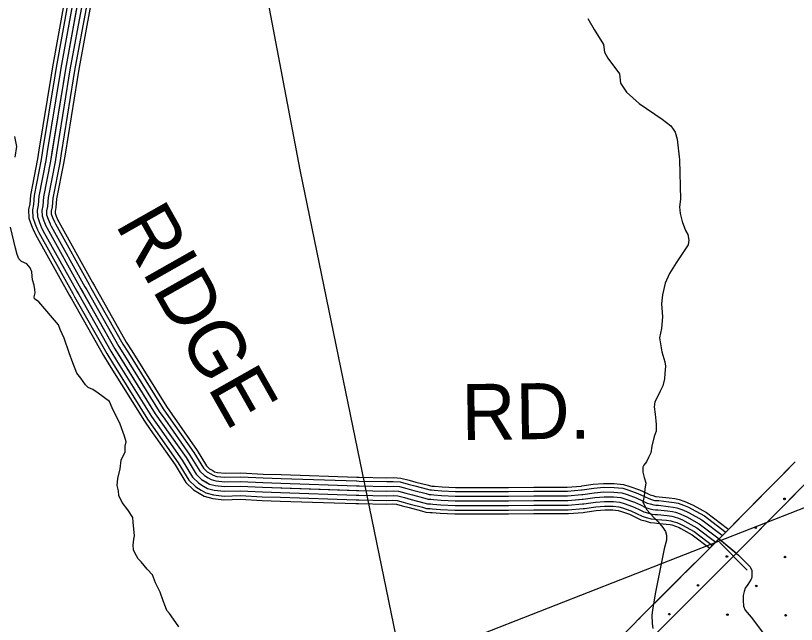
# Model space of a CAD drawing. Extents: x 1577619 to 1828281, y 483481 to 598136.
# Drawn here: x 1684780 to 1689939, y 520679 to 524700 of the extents above; entities that cross this region are included whole.
import ezdxf

# ---------------------------------------------------------------- set-up
doc = ezdxf.new("R2010")
doc.units = 0
for name, color, linetype in [('DESIGN - CENTERLINE - Proposed Text', 7, 'Continuous'), ('DESIGN - CONTOURS - Intermediate with optional Text', 7, 'Continuous'), ('DESIGN - EROSION CONTROL - Devices', 7, 'Continuous'), ('DESIGN - ROW - Right-of-Way and Easement Labels', 7, 'Continuous'), ('DESIGN - TRANSPORTATION - Text', 7, 'Continuous'), ('SURVEY - CENTERLINE - Preliminary Text', 7, 'Continuous'), ('SURVEY - DRAINAGE - Area Shapes', 7, 'Continuous'), ('SURVEY - TRANSPORTATION - Roads', 7, 'Continuous'), ('SURVEY - VEGETATION - Features with Text', 7, 'Continuous')]:
    doc.layers.add(name, color=color, linetype=linetype)

msp = doc.modelspace()

# ---------------------------------------------------------------- linework, layer by layer
at = {"layer": 'DESIGN - CENTERLINE - Proposed Text'}
for q in [(1697294.5, 524306.5), (1695618, 523650.8)]:
    msp.add_line((1681456.9, 518112.3), q, dxfattribs=at)
at = {"layer": 'DESIGN - CONTOURS - Intermediate with optional Text'}
msp.add_line((1689614.1, 521037.7), (1689430.4, 521221.7), dxfattribs=at)
for points in [[(1687255, 518732.8), (1688399.1, 519989.9), (1689031.6, 520639.6), (1689595.9, 521203.2), (1690042.2, 521653.7)], [(1689522.2, 521129.7), (1689595.9, 521203.2), (1689987.2, 521598.1)], [(1689055.2, 520663.3), (1689522.2, 521129.7)]]:
    msp.add_lwpolyline(points, dxfattribs=at)
at = {"layer": 'DESIGN - EROSION CONTROL - Devices'}
for centre in [(1689860.1, 521508.1), (1689669.7, 521317.7), (1689479.3, 521127.3), (1689863.9, 521123.5), (1689288.9, 520936.9), (1689673.5, 520933.1), (1689098.5, 520746.4), (1689483.1, 520742.7), (1689867.6, 520739)]:
    msp.add_circle(centre, 5.28, dxfattribs=at)
at = {"layer": 'DESIGN - TRANSPORTATION - Text'}
for points in [[(1688561.2, 524681), (1688603.3, 524609.7), (1688664.2, 524508.8), (1688671.7, 524458.6), (1688693.3, 524418.2), (1688770.3, 524315.2), (1688775.6, 524254.9), (1688815, 524194.4), (1688900.3, 524119.3), (1689051.3, 524017.4), (1689108.8, 523972.7), (1689124.6, 523950.5), (1689138.4, 523930.3), (1689151.9, 523884), (1689166.5, 523747.5), (1689171.8, 523488.7), (1689167.2, 523436.6), (1689170.7, 523392.5), (1689184.2, 523340.2), (1689205.6, 523279.8), (1689221.3, 523253.6), (1689228.9, 523217.4), (1689224.6, 523187.3), (1689198.2, 523147.5), (1689143.3, 523067.9), (1689100.5, 522996.1), (1689071.8, 522932.3), (1689055, 522856.2), (1689048.3, 522796.1), (1689053.4, 522709.8), (1689046.6, 522633.7), (1689034, 522571.7), (1689049, 522479.3), (1689068.3, 522412.9), (1689074, 522384.7), (1689069.5, 522336.7), (1689067.1, 522300.6), (1689056.6, 522254.6), (1689038.2, 522218.7), (1689019.8, 522178.7), (1689003.5, 522148.8), (1688999.1, 522116.8), (1689004.6, 522068.6), (1689010.2, 522024.4), (1689011.9, 521998.3), (1689011.4, 521956.2), (1688999.1, 521920.3), (1688984.4, 521856.2), (1688975.9, 521812.2), (1688961.5, 521780.3), (1688947.2, 521752.4), (1688931, 521730.5), (1688924.9, 521718.5), (1688924.5, 521684.4), (1688932.1, 521648.2), (1688943.8, 521614), (1688937.3, 521572), (1688932.8, 521525.9), (1688924.4, 521485.9), (1688949.9, 521435.5), (1688997.4, 521384.8), (1689025.1, 521356.5), (1689056.7, 521320), (1689074.4, 521291.8), (1689080.2, 521267.6), (1689079.8, 521235.6), (1689065.2, 521177.6), (1689006.1, 520881.4), (1688986.9, 520773.3), (1688982.5, 520739.2), (1688986, 520685.1), (1688989.6, 520650.9)], [(1684776.5, 523764.5), (1684788.8, 523835.5), (1684773.5, 523901.9)], [(1685499, 521922.9), (1685469.8, 522001.4), (1685416.9, 522110.3), (1685399.4, 522150.6), (1685324.1, 522206.8), (1685290.1, 522229.9), (1685258.3, 522244.3), (1685240.4, 522262.5), (1685210.9, 522305), (1685185.2, 522339.3), (1685157.9, 522405.8), (1685134.6, 522472.2), (1685099.6, 522568.9), (1685074.2, 522627.3), (1685062.5, 522657.5), (1684932, 522809.3), (1684910.2, 522825.5), (1684904.2, 522829.6), (1684902.4, 522843.7), (1684908.7, 522869.7), (1684906.9, 522891.7), (1684901.2, 522919.9), (1684891.6, 522956.1), (1684889.8, 522978.2), (1684886.1, 523008.3), (1684876.4, 523034.5), (1684852.7, 523060.8), (1684818.8, 523077.2), (1684801, 523093.4), (1684789.3, 523121.6), (1684779.7, 523163.8), (1684745.4, 523302.3)], [(1685857.9, 520663.7), (1685822.4, 520714.3), (1685796.8, 520750.6), (1685779, 520770.9), (1685769.2, 520795), (1685755.6, 520835.3), (1685734.2, 520891.7), (1685702.9, 520954.2), (1685683.4, 521006.5), (1685649.8, 521043), (1685610.3, 521091.5), (1685590.5, 521111.8), (1685566.9, 521152.1), (1685559.1, 521172.3), (1685557.4, 521202.4), (1685561.8, 521242.4), (1685564.1, 521264.5), (1685557, 521354.8), (1685553.3, 521384.9), (1685521.8, 521435.4), (1685484.3, 521483.9), (1685460.8, 521530.3), (1685459.1, 521560.4), (1685451.5, 521596.5), (1685454, 521642.6), (1685470.7, 521706.6), (1685477.3, 521762.7), (1685503.9, 521818.6), (1685504.3, 521856.7), (1685510.6, 521884.7), (1685499, 521922.9)]]:
    msp.add_lwpolyline(points, dxfattribs=at)
at = {"layer": 'SURVEY - CENTERLINE - Preliminary Text'}
for points in [[(1687420, 519988), (1686659.5, 523681.4), (1686272.5, 525723.1), (1686266.6, 525758.2), (1686265.3, 525791), (1686255.6, 526135), (1686301.1, 527011.8)], [(1687420, 519988), (1686659.5, 523681.4), (1686272.5, 525723.1), (1686266.6, 525758.2), (1686265.3, 525791), (1686255.6, 526135), (1686275.1, 526510.7)]]:
    msp.add_lwpolyline(points, dxfattribs=at)
at = {"layer": 'SURVEY - DRAINAGE - Area Shapes'}
for points in [[(1689427.4, 521243.8), (1689557.1, 521136.3), (1689630.3, 521061.3), (1689640.2, 521045.2), (1689643.2, 521035.6), (1689644, 521025.1), (1689643.7, 521005), (1689643.2, 520994.2), (1689641.5, 520983), (1689638.9, 520977.2), (1689617.1, 520943.1)], [(1689617.1, 520943.1), (1689600.8, 520919.2), (1689592.6, 520897.3), (1689586.3, 520869.3), (1689586, 520839.2), (1689589.5, 520799), (1689600.6, 520772.2), (1689638.8, 520726.3), (1689814.5, 520495.9), (1690430.1, 519669.2), (1690816.8, 519145.7), (1691181.8, 518654.5), (1691546.8, 518163.4), (1691631.7, 518054.2), (1691660.1, 518016.4)]]:
    msp.add_lwpolyline(points, dxfattribs=at)
at = {"layer": 'SURVEY - TRANSPORTATION - Roads'}
for points in [[(1685193.4, 524810), (1685108.4, 524347.6), (1685009.9, 523739), (1684963.4, 523502.8), (1684958.8, 523444.7), (1684952.4, 523412.7), (1684954.1, 523378.6), (1684965.7, 523344.4), (1684979.4, 523312.1), (1684987.7, 523295.9), (1685211.1, 522894.6), (1685435.1, 522499.2), (1685702.7, 522069.2), (1685905.7, 521780.3), (1685972.6, 521671.3), (1686008.3, 521636.8), (1686060, 521606.2), (1686097.9, 521595.8), (1686159.9, 521589.1), (1686265.9, 521592), (1686412, 521584.4), (1687048.1, 521563.7), (1687231.9, 521559.9), (1687274.2, 521561.3), (1687310.2, 521559), (1687357.1, 521546), (1687402, 521533.9), (1687484.3, 521512.9), (1687505.8, 521506.8), (1687539.8, 521504.4), (1687591.8, 521499.9), (1687683.8, 521494.9), (1688036, 521495.2), (1688204.1, 521497.4), (1688428.2, 521497.1), (1688530.4, 521506), (1688606.6, 521517.3), (1688668.6, 521522.6), (1688730.9, 521522.2), (1688778.7, 521517.5), (1688810.6, 521507.1), (1688868.4, 521486.5), (1688908.2, 521468), (1688942.1, 521451.6), (1688964, 521445.3), (1688989.9, 521437), (1689023.9, 521434.7), (1689087.9, 521428), (1689119.9, 521423.7), (1689139.8, 521419.4), (1689169.7, 521409.1), (1689199.6, 521396.7), (1689215.5, 521388.6), (1689297.1, 521343.6), (1689428.1, 521243.9), (1689544.4, 521146.9)], [(1685103.3, 524799.7), (1685023, 524362.4), (1685013.9, 524306)], [(1685127.6, 524795.3), (1685047.3, 524358.1), (1685038.3, 524302)], [(1685158.1, 524789.7), (1685077.9, 524352.9), (1685068.9, 524297)], [(1685188.6, 524784.1), (1685108.4, 524347.6), (1685099.5, 524292.1)], [(1685219.1, 524778.5), (1685139, 524342.3), (1685130.1, 524287.1)], [(1685249.6, 524772.9), (1685169.5, 524337), (1685160.7, 524282.2)], [(1685274.9, 524768.2), (1685194.9, 524332.7), (1685186, 524278.1)], [(1685013.9, 524306), (1684934, 523812.4)], [(1685038.3, 524302), (1684958.4, 523808.4)], [(1685068.9, 524297.1), (1684989, 523803.5)], [(1685099.5, 524292.1), (1685019.6, 523798.5)], [(1685130.1, 524287.2), (1685050.2, 523793.6)], [(1685160.7, 524282.2), (1685080.8, 523788.6)], [(1685186, 524278.1), (1685106.2, 523784.5)], [(1684934, 523812.4), (1684924.6, 523754.3), (1684877.4, 523514.7), (1684872.7, 523456.6), (1684865.3, 523419.1), (1684868, 523362.2), (1684884.7, 523313.4), (1684900.8, 523275.4), (1684903.5, 523270.2)], [(1684958.4, 523808.4), (1684948.9, 523749.9), (1684901.9, 523511.3), (1684897.3, 523453.2), (1684890.2, 523417.3), (1684892.6, 523366.9), (1684907.8, 523322.2), (1684923.2, 523285.9), (1684925.5, 523281.4)], [(1684989, 523803.5), (1684979.4, 523744.4), (1684932.6, 523507.1), (1684928, 523449), (1684921.3, 523415), (1684923.3, 523372.7), (1684936.7, 523333.3), (1684951.3, 523299), (1684953.1, 523295.6)], [(1685019.6, 523798.5), (1685009.9, 523739), (1684963.4, 523502.8), (1684958.8, 523444.7), (1684952.4, 523412.7), (1684954.1, 523378.6), (1684965.7, 523344.4), (1684979.4, 523312.1), (1684980.6, 523309.7)], [(1685050.2, 523793.6), (1685040.4, 523733.5), (1684994.2, 523498.6), (1684989.5, 523440.5), (1684983.6, 523410.4), (1684984.8, 523384.4), (1684994.7, 523355.4), (1685007.5, 523325.3), (1685008.2, 523323.8)], [(1685080.8, 523788.6), (1685071, 523728), (1685024.9, 523494.3), (1685020.3, 523436.2), (1685014.7, 523408.1), (1685015.6, 523390.3), (1685023.7, 523366.5), (1685035.6, 523338.4), (1685035.8, 523337.9)], [(1685106.2, 523784.5), (1685096.3, 523723.5), (1685050.4, 523490.8), (1685045.8, 523432.7), (1685040.6, 523406.2), (1685041.1, 523395.1), (1685047.7, 523375.7), (1685058.9, 523349.3)], [(1685008.2, 523323.8), (1685015.1, 523310.5), (1685238.1, 522909.8), (1685250.5, 522888)], [(1685035.8, 523338), (1685042.4, 523325.1), (1685265.2, 522924.9), (1685277.5, 522903.2)], [(1685058.7, 523349.7), (1685065.1, 523337.2), (1685287.6, 522937.5), (1685299.8, 522915.9)], [(1684903.5, 523270.2), (1684911.2, 523255), (1685135.5, 522852.1), (1685148.1, 522829.9)], [(1684925.5, 523281.4), (1684933, 523266.7), (1685157.1, 522864.2), (1685169.6, 522842.1)], [(1684953, 523295.6), (1684960.4, 523281.3), (1685184.1, 522879.4), (1685196.5, 522857.4)], [(1684980.6, 523309.7), (1684987.7, 523295.9), (1685211.1, 522894.6), (1685223.5, 522872.7)], [(1685299.8, 522915.9), (1685510.5, 522544), (1685546.9, 522485.5)], [(1685196.5, 522857.4), (1685408.4, 522483.3), (1685446.1, 522422.7)], [(1685223.5, 522872.7), (1685435.1, 522499.2), (1685472.4, 522439.1)], [(1685250.5, 522888), (1685461.7, 522515), (1685498.7, 522455.5)], [(1685277.5, 522903.2), (1685488.4, 522530.8), (1685525.1, 522471.9)], [(1685148.1, 522829.9), (1685360.5, 522454.9), (1685398.8, 522393.3)], [(1685169.6, 522842.1), (1685381.7, 522467.5), (1685419.8, 522406.3)], [(1685498.7, 522455.5), (1685728.5, 522086.3), (1685765, 522034.4)], [(1685525.1, 522471.9), (1685754.4, 522103.4), (1685790.4, 522052.3)], [(1685546.9, 522485.5), (1685775.8, 522117.6), (1685811.4, 522067)], [(1685398.8, 522393.3), (1685630.3, 522021.3), (1685668.7, 521966.7)], [(1685419.8, 522406.4), (1685650.9, 522035), (1685688.9, 521981)], [(1685446.1, 522422.7), (1685676.8, 522052.1), (1685714.3, 521998.8)], [(1685472.4, 522439.1), (1685702.7, 522069.2), (1685739.6, 522016.6)], [(1685765, 522034.4), (1685931.6, 521797.3), (1685997, 521690.8), (1686027.2, 521661.6), (1686053, 521646.3)], [(1685790.3, 522052.3), (1685957.6, 521814.4), (1686021.3, 521710.4), (1686046.1, 521686.5), (1686068.8, 521673)], [(1685811.4, 522067.1), (1685979.1, 521828.5), (1686041.6, 521726.6), (1686061.8, 521707), (1686081.9, 521695.2)], [(1685688.9, 521981), (1685853.9, 521746.2), (1685923.9, 521632.2), (1685970.4, 521587.2), (1686005.6, 521566.3)], [(1685714.3, 521998.8), (1685879.8, 521763.2), (1685948.2, 521651.7), (1685989.3, 521612), (1686021.4, 521593)], [(1685739.6, 522016.6), (1685905.7, 521780.3), (1685972.6, 521671.3), (1686008.3, 521636.8), (1686037.2, 521619.7)], [(1685668.7, 521966.7), (1685833.2, 521732.6), (1685904.4, 521616.6), (1685955.3, 521567.4), (1685993.1, 521545)], [(1686068.8, 521673), (1686084.4, 521663.8), (1686109.5, 521656.9), (1686162.3, 521651.2), (1686266.7, 521654), (1686414.6, 521646.4), (1686533.5, 521642.5)], [(1686081.9, 521695.2), (1686094.6, 521687.7), (1686114.3, 521682.2), (1686163.4, 521676.9), (1686267, 521679.8), (1686415.7, 521672.1), (1686534.3, 521668.2)], [(1686037.2, 521619.7), (1686060, 521606.2), (1686097.9, 521595.8), (1686159.9, 521589.1), (1686265.9, 521592), (1686412, 521584.4), (1686531.4, 521580.5)], [(1686053, 521646.4), (1686072.2, 521635), (1686103.7, 521626.3), (1686161.1, 521620.1), (1686266.3, 521623), (1686413.3, 521615.4), (1686532.5, 521611.5)], [(1686533.4, 521642.5), (1687033.2, 521626.2)], [(1686534.3, 521668.2), (1687034, 521651.9)], [(1687033.1, 521626.2), (1687049.8, 521625.7), (1687231.5, 521622), (1687275.2, 521623.4), (1687320.6, 521620.4), (1687373.4, 521605.8), (1687417.7, 521593.9), (1687500.5, 521572.8), (1687516.5, 521568.2), (1687528.4, 521567.4)], [(1687034, 521651.9), (1687050.4, 521651.4), (1687231.4, 521647.7), (1687275.7, 521649.2), (1687324.9, 521645.9), (1687380.2, 521630.7), (1687424.3, 521618.8), (1687507.2, 521597.6), (1687521, 521593.6), (1687530.2, 521593)], [(1686021.4, 521593), (1686047.8, 521577.4), (1686092.1, 521565.2), (1686158.6, 521558.1), (1686265.6, 521561), (1686410.7, 521553.5), (1686530.4, 521549.6)], [(1686531.4, 521580.5), (1687031.2, 521564.3)], [(1686532.4, 521611.5), (1687032.2, 521595.3)], [(1687032.1, 521595.3), (1687048.9, 521594.7), (1687231.7, 521590.9), (1687274.7, 521592.4), (1687315.4, 521589.7), (1687365.3, 521575.9), (1687409.9, 521563.9), (1687492.4, 521542.8), (1687511.2, 521537.5), (1687526.2, 521536.4)], [(1687528.4, 521567.4), (1687544.6, 521566.2), (1687596.1, 521561.7), (1687685.4, 521556.9), (1688023.6, 521557.2)], [(1687530.1, 521593), (1687546.6, 521591.9), (1687598, 521587.4), (1687686.1, 521582.6), (1688023.6, 521582.9)], [(1688023.6, 521582.9), (1688035.4, 521582.9), (1688203.6, 521585.2), (1688424.5, 521584.8), (1688515.6, 521592.8)], [(1688023.6, 521557.2), (1688035.5, 521557.2), (1688203.7, 521559.4), (1688425.6, 521559.1), (1688517.9, 521567.2)], [(1688515.6, 521592.8), (1688520.2, 521593.2), (1688596.4, 521604.5), (1688665.2, 521610.4), (1688735.5, 521609.9), (1688796.7, 521603.9), (1688838.9, 521590.2), (1688901.7, 521567.7), (1688945.8, 521547.3), (1688973.4, 521533.9), (1688989.4, 521529.3), (1689006.6, 521523.8), (1689012.7, 521523.4)], [(1688517.8, 521567.2), (1688523.2, 521567.6), (1688599.4, 521578.9), (1688666.2, 521584.7), (1688734.2, 521584.1), (1688791.4, 521578.5), (1688830.6, 521565.8), (1688891.9, 521543.9), (1688934.8, 521524), (1688964.2, 521509.7), (1688981.9, 521504.7), (1689001.7, 521498.4), (1689010.9, 521497.7)], [(1685993, 521545.1), (1686025.8, 521525.7), (1686081.7, 521510.3), (1686156.4, 521502.3), (1686264.9, 521505.2), (1686408.3, 521497.8), (1686528.6, 521493.9)], [(1686005.6, 521566.3), (1686035.5, 521548.6), (1686086.3, 521534.7), (1686157.4, 521527), (1686265.2, 521529.9), (1686409.4, 521522.5), (1686529.4, 521518.6)], [(1686529.4, 521518.6), (1687029.1, 521502.3)], [(1686530.4, 521549.6), (1687030.1, 521533.3)], [(1687030.1, 521533.3), (1687047.3, 521532.7), (1687232.1, 521528.9), (1687273.7, 521530.3), (1687305, 521528.2), (1687349, 521516.1), (1687394.1, 521504), (1687476.2, 521483), (1687500.4, 521476.1), (1687521.9, 521474.6)], [(1687031.1, 521564.3), (1687048.1, 521563.7), (1687231.9, 521559.9), (1687274.2, 521561.3), (1687310.2, 521559), (1687357.1, 521546), (1687402, 521533.9), (1687484.3, 521512.9), (1687505.8, 521506.8), (1687524.1, 521505.5)], [(1687526.2, 521536.4), (1687542.2, 521535.3), (1687593.9, 521530.8), (1687684.6, 521525.9), (1688023.7, 521526.2)], [(1688023.6, 521526.2), (1688035.8, 521526.2), (1688203.9, 521528.4), (1688426.9, 521528.1), (1688520.6, 521536.3)], [(1688520.5, 521536.3), (1688526.8, 521536.8), (1688602.9, 521548.1), (1688667.4, 521553.7), (1688732.5, 521553.2), (1688785, 521548), (1688820.6, 521536.5), (1688880.1, 521515.2), (1688921.5, 521496), (1688953.1, 521480.7), (1688973, 521475), (1688995.8, 521467.7), (1689008.8, 521466.8)], [(1688523.3, 521505.4), (1688530.4, 521506), (1688606.6, 521517.3), (1688668.6, 521522.6), (1688730.9, 521522.2), (1688778.7, 521517.5), (1688810.6, 521507.1), (1688868.4, 521486.5), (1688908.2, 521468), (1688942.1, 521451.6), (1688964, 521445.3), (1688989.9, 521437), (1689006.7, 521435.9)], [(1689012.7, 521523.4), (1689031.5, 521522.1), (1689098.4, 521515.1), (1689134.9, 521510.1), (1689163.3, 521504.1), (1689200.8, 521491.1), (1689236.5, 521476.4), (1689256.8, 521466), (1689345.1, 521417.3), (1689482.8, 521312.6), (1689490, 521306.6)], [(1686528.6, 521493.9), (1687028.3, 521477.6)], [(1687028.3, 521477.6), (1687045.8, 521477), (1687232.5, 521473.2), (1687272.8, 521474.5), (1687295.7, 521473), (1687334.3, 521462.4), (1687380, 521450.1), (1687461.7, 521429.2), (1687490.7, 521420.9), (1687518, 521419)], [(1687029.1, 521502.3), (1687046.5, 521501.7), (1687232.3, 521497.9), (1687273.2, 521499.3), (1687299.8, 521497.5), (1687340.8, 521486.2), (1687386.3, 521474), (1687468.1, 521453), (1687495, 521445.4), (1687519.8, 521443.7)], [(1687521.9, 521474.6), (1687537.4, 521473.5), (1687589.6, 521468.9), (1687682.9, 521463.9), (1688023.7, 521464.2)], [(1687524.1, 521505.5), (1687539.8, 521504.4), (1687591.8, 521499.9), (1687683.8, 521494.9), (1688023.7, 521495.2)], [(1688023.7, 521495.2), (1688036, 521495.2), (1688204.1, 521497.4), (1688428.2, 521497.1), (1688523.3, 521505.4)], [(1688023.7, 521464.2), (1688036.2, 521464.2), (1688204.3, 521466.4), (1688429.6, 521466.1), (1688526, 521474.5)], [(1688526, 521474.5), (1688534, 521475.2), (1688610.2, 521486.5), (1688669.9, 521491.6), (1688729.3, 521491.2), (1688772.3, 521487), (1688800.6, 521477.8), (1688856.6, 521457.7), (1688894.9, 521440), (1688931, 521422.5), (1688955, 521415.7), (1688984, 521406.4), (1689004.5, 521405)], [(1689008.8, 521466.8), (1689026.6, 521465.6), (1689091.6, 521458.8), (1689125.2, 521454.2), (1689148.1, 521449.4), (1689180.7, 521438.1), (1689212.7, 521424.9), (1689230.1, 521415.9), (1689314.1, 521369.6), (1689447.5, 521268.2), (1689450, 521266.1)], [(1689010.9, 521497.7), (1689029.3, 521496.5), (1689095.3, 521489.6), (1689130.5, 521484.8), (1689156.4, 521479.3), (1689191.7, 521467.1), (1689225.7, 521453.1), (1689244.7, 521443.3), (1689331, 521395.7), (1689466.8, 521292.4), (1689471.9, 521288.2)], [(1687518.1, 521419), (1687533, 521418), (1687585.6, 521413.3), (1687681.5, 521408.2), (1688023.8, 521408.5)], [(1687519.8, 521443.7), (1687534.9, 521442.6), (1687587.4, 521438), (1687682.1, 521432.9), (1688023.7, 521433.2)], [(1688023.7, 521433.2), (1688036.4, 521433.2), (1688204.5, 521435.4), (1688430.9, 521435.1), (1688528.7, 521443.7)], [(1688023.7, 521408.5), (1688036.6, 521408.5), (1688204.6, 521410.7), (1688432, 521410.4), (1688530.8, 521419)], [(1688528.7, 521443.7), (1688537.6, 521444.4), (1688613.8, 521455.7), (1688671.1, 521460.6), (1688727.6, 521460.2), (1688765.9, 521456.4), (1688790.5, 521448.4), (1688844.9, 521429), (1688881.6, 521412), (1688919.9, 521393.4), (1688946.1, 521386), (1688978.2, 521375.7), (1689002.4, 521374)], [(1688530.8, 521419), (1688540.5, 521419.9), (1688616.6, 521431.1), (1688672, 521435.9), (1688726.3, 521435.5), (1688760.8, 521432.1), (1688782.6, 521425), (1688835.5, 521406.1), (1688871.1, 521389.6), (1688911.1, 521370.2), (1688938.9, 521362.3), (1688973.5, 521351.3), (1689000.7, 521349.4)], [(1689006.6, 521435.9), (1689023.9, 521434.7), (1689087.9, 521428), (1689119.9, 521423.7), (1689139.8, 521419.4), (1689169.7, 521409.1), (1689199.6, 521396.7), (1689215.5, 521388.6), (1689297.1, 521343.6), (1689427.8, 521244.2)], [(1689002.3, 521374), (1689018.5, 521372.9), (1689080.5, 521366.4), (1689109.3, 521362.5), (1689123.2, 521359.6), (1689147.8, 521351.1), (1689173.6, 521340.4), (1689186.4, 521333.8), (1689263.2, 521291.5), (1689383.6, 521199.9)], [(1689004.5, 521405), (1689021.2, 521403.8), (1689084.2, 521397.2), (1689114.6, 521393.1), (1689131.5, 521389.5), (1689158.7, 521380.1), (1689186.6, 521368.6), (1689201, 521361.2), (1689280.2, 521317.5), (1689405.8, 521222)], [(1689000.6, 521349.4), (1689016.4, 521348.3), (1689077.5, 521341.9), (1689105, 521338.2), (1689116.6, 521335.7), (1689139, 521328), (1689163.2, 521318), (1689174.8, 521312), (1689249.7, 521270.7), (1689365.7, 521182.4)]]:
    msp.add_lwpolyline(points, dxfattribs=at)
at = {"layer": 'SURVEY - VEGETATION - Features with Text'}
for points in [[(1688133.4, 519928.9), (1688920.5, 520737.6), (1689485.6, 521302), (1689931.5, 521751.9)], [(1689852.2, 521671.9), (1689931.5, 521751.9)], [(1689560.8, 521377.9), (1689746.6, 521565.4)], [(1689374.4, 521190.9), (1689485.6, 521302), (1689560.8, 521377.9)], [(1689081.5, 520898.3), (1689268.3, 521084.9)], [(1688895.1, 520711.4), (1688920.5, 520737.6), (1689081.5, 520898.3)]]:
    msp.add_lwpolyline(points, dxfattribs=at)

# ---------------------------------------------------------------- texts
at = {"layer": 'DESIGN - ROW - Right-of-Way and Easement Labels'}
for s, height, rotation, p in [('RIDGE', 370, 299.5254, (1685434.4, 523321.6)), ('RD.', 369.99, 0.7635, (1687728, 521895.9))]:
    msp.add_text(s, height=height, rotation=rotation, dxfattribs=at).set_placement(p)

doc.saveas('drawing.dxf')
